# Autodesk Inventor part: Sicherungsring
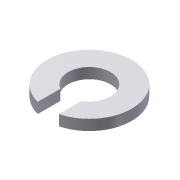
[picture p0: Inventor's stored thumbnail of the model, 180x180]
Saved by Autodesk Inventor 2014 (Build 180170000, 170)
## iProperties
Created: 2013-01
Part Number: Sicherungsring
Material: Aluminum 6061
Document SubType Name: Modeling
Designer: banachd
Density: 1 g/cm^3
Description: 2 mm RETAINING RING
Appearance: Aluminium - flach
Author: banachd
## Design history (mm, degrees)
sketch "Skizze1"
  geometry: L1 (-0.5, -0.866)-(-0.5, -1.936); L2 (0.5, -0.866)-(0.5, -1.936); A1 r 1 centre (0, 0) between (0.5, -0.866) and (-0.5, -0.866); A2 r 2 centre (0, 0) between (0.5, -1.936) and (-0.5, -1.936); 1 further point
  constraints: 4 end point, 4 point on circle, 2 centre point, 2 coincident, 2 vertical, 1 horizontal alignment
  dimensions: "d0" = 2 diameter of A1; "d1" = 4 diameter of A2; "d28" = 1 distance of L2.end L1.end
extrude "Extrusion1" new body sketch "Skizze1" distance "d29" = 0.5; taper "d30" = 0 deg
body "Solid1"
other parameters: "d13" = 18.5 [user parameter], "d14" = 4.45 [user parameter], "d15" = 0.67 [user parameter], "d16" = 2 [user parameter], "d17" = 2.68 [user parameter], "d18" = 8.5 [user parameter], "d19" = 11.2 [user parameter], "d20" = 2.5 [user parameter], "d21" = 4.5 [user parameter], "d22" = 14.5 [user parameter], "d23" = 6
